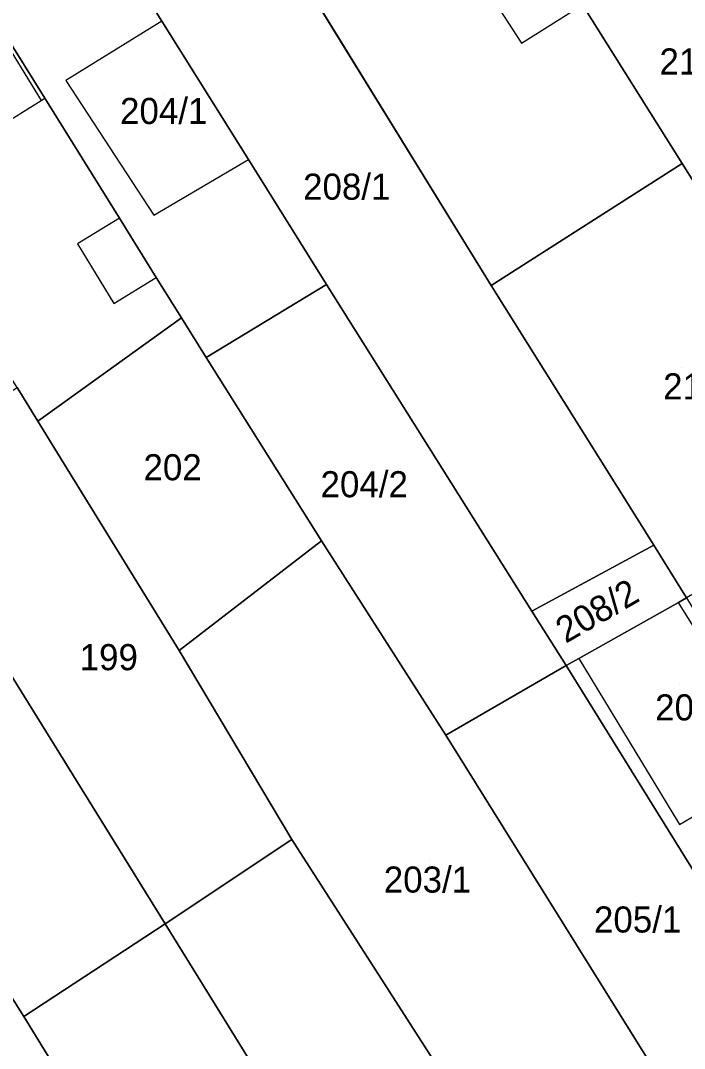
# Model space of a CAD drawing. Extents: x -263943 to -261149, y -1236934 to -1230686.
# Drawn here: x -262330.7 to -262279.9, y -1235708.9 to -1235630.2 of the extents above; entities that cross this region are included whole.
import ezdxf

# ---------------------------------------------------------------- set-up
doc = ezdxf.new("R2010")
doc.units = 0
for name, color, linetype in [('body_kn', 7, 'Continuous'), ('kladpar_druhypozemkov', 7, 'Continuous'), ('kladpar_hranice', 7, 'Continuous'), ('kladpar_parcelnecisla', 7, 'Continuous'), ('kladpar_plochy', 7, 'Continuous'), ('zappar_hrandruhpozemk', 7, 'Continuous')]:
    doc.layers.add(name, color=color, linetype=linetype)

msp = doc.modelspace()

# ---------------------------------------------------------------- linework, layer by layer
at = {"layer": 'body_kn'}
for p, q in [((-262319.91, -1235630.21), (-262319.91, -1235630.21)), ((-262319.91, -1235630.21), (-262319.91, -1235630.21)), ((-262292.36, -1235631.92), (-262292.36, -1235631.92)), ((-262327.26, -1235634.76), (-262327.26, -1235634.76)), ((-262327.26, -1235634.76), (-262327.26, -1235634.76)), ((-262329.16, -1235636.29), (-262329.16, -1235636.29)), ((-262329.16, -1235636.29), (-262329.16, -1235636.29)), ((-262328.88, -1235636.12), (-262328.88, -1235636.12)), ((-262313.29, -1235640.82), (-262313.29, -1235640.82)), ((-262280.06, -1235641.13), (-262280.06, -1235641.13)), ((-262280.06, -1235641.13), (-262280.06, -1235641.13)), ((-262323.16, -1235645.31), (-262323.16, -1235645.31)), ((-262323.16, -1235645.31), (-262323.16, -1235645.31)), ((-262320.54, -1235645.08), (-262320.54, -1235645.08)), ((-262326.38, -1235647.29), (-262326.38, -1235647.29)), ((-262320.34, -1235649.85), (-262320.34, -1235649.85)), ((-262307.31, -1235650.4), (-262307.31, -1235650.4)), ((-262307.31, -1235650.4), (-262307.31, -1235650.4)), ((-262294.69, -1235650.47), (-262294.69, -1235650.47)), ((-262323.58, -1235651.86), (-262323.58, -1235651.86)), ((-262318.41, -1235652.95), (-262318.41, -1235652.95)), ((-262318.41, -1235652.95), (-262318.41, -1235652.95)), ((-262316.53, -1235656), (-262316.53, -1235656)), ((-262329.41, -1235660.86), (-262329.41, -1235660.86)), ((-262328.1, -1235662.99), (-262328.1, -1235662.99)), ((-262307.69, -1235670.04), (-262307.69, -1235670.04)), ((-262307.69, -1235670.04), (-262307.69, -1235670.04)), ((-262282.25, -1235670.38), (-262282.25, -1235670.38)), ((-262280.36, -1235674.76), (-262280.36, -1235674.76)), ((-262291.57, -1235675.42), (-262291.57, -1235675.42)), ((-262318.6, -1235678.44), (-262318.6, -1235678.44)), ((-262318.6, -1235678.44), (-262318.6, -1235678.44)), ((-262287.99, -1235679.05), (-262287.99, -1235679.05)), ((-262287.99, -1235679.05), (-262287.99, -1235679.05)), ((-262288.95, -1235679.59), (-262288.95, -1235679.59)), ((-262298.17, -1235684.93), (-262298.17, -1235684.93)), ((-262298.17, -1235684.93), (-262298.17, -1235684.93)), ((-262280.28, -1235691.77), (-262280.28, -1235691.77)), ((-262309.95, -1235692.93), (-262309.95, -1235692.93)), ((-262309.95, -1235692.93), (-262309.95, -1235692.93)), ((-262319.66, -1235699.37), (-262319.66, -1235699.37)), ((-262330.48, -1235706.48), (-262330.48, -1235706.48)), ((-262330.48, -1235706.48), (-262330.48, -1235706.48))]:
    msp.add_line(p, q, dxfattribs=at)
at = {"layer": 'kladpar_druhypozemkov'}
for p, q in [((-262319.82, -1235635.85), (-262319.82, -1235635.85)), ((-262305.97, -1235641.7), (-262305.97, -1235641.7)), ((-262280.12, -1235656.75), (-262280.12, -1235656.75)), ((-262318.92, -1235663.3), (-262318.92, -1235663.3)), ((-262303.92, -1235664.3), (-262303.92, -1235664.3)), ((-262286.01, -1235674.27), (-262286.01, -1235674.27)), ((-262324.82, -1235678), (-262324.82, -1235678)), ((-262280.27, -1235680.95), (-262280.27, -1235680.95)), ((-262299.41, -1235694.45), (-262299.41, -1235694.45)), ((-262283.57, -1235697.7), (-262283.57, -1235697.7))]:
    msp.add_line(p, q, dxfattribs=at)
at = {"layer": 'kladpar_hranice'}
for points in [[(-262290.13, -1235625.13), (-262287.71, -1235628.98), (-262280.06, -1235641.13), (-262294.69, -1235650.47), (-262318.5, -1235611.81), (-262304.03, -1235603.06), (-262303.72, -1235603.55), (-262302.21, -1235605.94), (-262301.25, -1235607.46), (-262295.34, -1235616.87), (-262294.09, -1235618.85), (-262290.45, -1235624.62), (-262290.13, -1235625.13)], [(-262307.31, -1235650.4), (-262313.29, -1235640.82), (-262319.91, -1235630.21), (-262327.8, -1235617.58), (-262318.5, -1235611.81), (-262294.69, -1235650.47), (-262282.25, -1235670.38), (-262291.57, -1235675.42), (-262307.31, -1235650.4)], [(-262318.41, -1235652.95), (-262320.34, -1235649.85), (-262323.16, -1235645.31), (-262328.88, -1235636.12), (-262335.26, -1235625.87), (-262336.93, -1235623.19), (-262327.8, -1235617.58), (-262319.91, -1235630.21), (-262313.29, -1235640.82), (-262307.31, -1235650.4), (-262316.53, -1235656), (-262318.41, -1235652.95)], [(-262280.06, -1235641.13), (-262287.71, -1235628.98), (-262290.13, -1235625.13), (-262290.45, -1235624.62), (-262281.56, -1235618.72), (-262266.88, -1235641.83), (-262266.34, -1235642.68), (-262275.56, -1235648.31), (-262280.06, -1235641.13)], [(-262323.16, -1235645.31), (-262320.34, -1235649.85), (-262318.41, -1235652.95), (-262329.41, -1235660.86), (-262330.99, -1235658.3), (-262340.45, -1235643.42), (-262345.87, -1235634.63), (-262348.61, -1235630.18), (-262336.93, -1235623.19), (-262335.26, -1235625.87), (-262328.88, -1235636.12), (-262323.16, -1235645.31)], [(-262279.73, -1235674.41), (-262282.25, -1235670.38), (-262294.69, -1235650.47), (-262280.06, -1235641.13), (-262275.56, -1235648.31), (-262264.67, -1235665.67), (-262279.73, -1235674.41)], [(-262307.69, -1235670.04), (-262316.53, -1235656), (-262307.31, -1235650.4), (-262291.57, -1235675.42), (-262288.95, -1235679.59), (-262298.17, -1235684.93), (-262307.69, -1235670.04)], [(-262318.6, -1235678.44), (-262328.1, -1235662.99), (-262329.41, -1235660.86), (-262318.41, -1235652.95), (-262316.53, -1235656), (-262307.69, -1235670.04), (-262318.6, -1235678.44)], [(-262341.16, -1235664.74), (-262340.86, -1235664.55), (-262337.86, -1235662.65), (-262330.99, -1235658.3), (-262329.41, -1235660.86), (-262328.1, -1235662.99), (-262318.6, -1235678.44), (-262309.95, -1235692.93), (-262319.66, -1235699.37), (-262339.3, -1235667.72), (-262341.16, -1235664.74)], [(-262330.48, -1235706.48), (-262344.85, -1235683.73), (-262347.49, -1235679.41), (-262353.7, -1235669.41), (-262355.74, -1235666.13), (-262343.21, -1235661.46), (-262341.16, -1235664.74), (-262339.3, -1235667.72), (-262319.66, -1235699.37), (-262330.48, -1235706.48)], [(-262294.44, -1235717.17), (-262296.06, -1235714.61), (-262309.95, -1235692.93), (-262318.6, -1235678.44), (-262307.69, -1235670.04), (-262298.17, -1235684.93), (-262282.68, -1235709.8), (-262291.47, -1235715.31), (-262294.44, -1235717.17)], [(-262287.99, -1235679.05), (-262288.95, -1235679.59), (-262291.57, -1235675.42), (-262282.25, -1235670.38), (-262279.73, -1235674.41), (-262280.36, -1235674.76), (-262287.99, -1235679.05)], [(-262287.99, -1235679.05), (-262280.36, -1235674.76), (-262279.73, -1235674.41), (-262269.35, -1235691.58), (-262278.15, -1235697.01), (-262288.95, -1235679.59), (-262287.99, -1235679.05)], [(-262298.17, -1235684.93), (-262288.95, -1235679.59), (-262278.15, -1235697.01), (-262268.04, -1235713.09), (-262277.09, -1235718.77), (-262282.68, -1235709.8), (-262298.17, -1235684.93)], [(-262338.23, -1235728.59), (-262350.56, -1235709.05), (-262361.01, -1235692.39), (-262344.85, -1235683.73), (-262330.48, -1235706.48), (-262322.66, -1235719.26), (-262338.23, -1235728.59)], [(-262309.95, -1235692.93), (-262296.06, -1235714.61), (-262306.57, -1235720.55), (-262319.66, -1235699.37), (-262309.95, -1235692.93)], [(-262330.48, -1235706.48), (-262319.66, -1235699.37), (-262306.57, -1235720.55), (-262303.44, -1235725.52), (-262300.62, -1235730), (-262299.02, -1235732.55), (-262309.91, -1235739.73), (-262322.66, -1235719.26), (-262330.48, -1235706.48)]]:
    msp.add_lwpolyline(points, dxfattribs=at)
at = {"layer": 'kladpar_plochy'}
for p, q in [((-262318.5, -1235611.81), (-262294.69, -1235650.47)), ((-262319.91, -1235630.21), (-262327.8, -1235617.58)), ((-262313.29, -1235640.82), (-262319.91, -1235630.21)), ((-262307.31, -1235650.4), (-262313.29, -1235640.82)), ((-262291.57, -1235675.42), (-262307.31, -1235650.4)), ((-262294.69, -1235650.47), (-262282.25, -1235670.38)), ((-262282.25, -1235670.38), (-262291.57, -1235675.42))]:
    msp.add_line(p, q, dxfattribs=at)
for points in [[(-262290.13, -1235625.13), (-262287.71, -1235628.98), (-262280.06, -1235641.13), (-262294.69, -1235650.47), (-262318.5, -1235611.81), (-262304.03, -1235603.06), (-262303.72, -1235603.55), (-262302.21, -1235605.94), (-262301.25, -1235607.46), (-262295.34, -1235616.87), (-262294.09, -1235618.85), (-262290.45, -1235624.62)], [(-262318.41, -1235652.95), (-262320.34, -1235649.85), (-262323.16, -1235645.31), (-262328.88, -1235636.12), (-262335.26, -1235625.87), (-262336.93, -1235623.19), (-262327.8, -1235617.58), (-262319.91, -1235630.21), (-262313.29, -1235640.82), (-262307.31, -1235650.4), (-262316.53, -1235656)], [(-262280.06, -1235641.13), (-262287.71, -1235628.98), (-262290.13, -1235625.13), (-262290.45, -1235624.62), (-262281.56, -1235618.72), (-262266.88, -1235641.83), (-262266.34, -1235642.68), (-262275.56, -1235648.31)], [(-262323.16, -1235645.31), (-262320.34, -1235649.85), (-262318.41, -1235652.95), (-262329.41, -1235660.86), (-262330.99, -1235658.3), (-262340.45, -1235643.42), (-262345.87, -1235634.63), (-262348.61, -1235630.18), (-262336.93, -1235623.19), (-262335.26, -1235625.87), (-262328.88, -1235636.12)], [(-262279.73, -1235674.41), (-262282.25, -1235670.38), (-262294.69, -1235650.47), (-262280.06, -1235641.13), (-262275.56, -1235648.31), (-262264.67, -1235665.67)], [(-262307.69, -1235670.04), (-262316.53, -1235656), (-262307.31, -1235650.4), (-262291.57, -1235675.42), (-262288.95, -1235679.59), (-262298.17, -1235684.93)], [(-262318.6, -1235678.44), (-262328.1, -1235662.99), (-262329.41, -1235660.86), (-262318.41, -1235652.95), (-262316.53, -1235656), (-262307.69, -1235670.04)], [(-262341.16, -1235664.74), (-262340.86, -1235664.55), (-262337.86, -1235662.65), (-262330.99, -1235658.3), (-262329.41, -1235660.86), (-262328.1, -1235662.99), (-262318.6, -1235678.44), (-262309.95, -1235692.93), (-262319.66, -1235699.37), (-262339.3, -1235667.72)], [(-262330.48, -1235706.48), (-262344.85, -1235683.73), (-262347.49, -1235679.41), (-262353.7, -1235669.41), (-262355.74, -1235666.13), (-262343.21, -1235661.46), (-262341.16, -1235664.74), (-262339.3, -1235667.72), (-262319.66, -1235699.37)], [(-262294.44, -1235717.17), (-262296.06, -1235714.61), (-262309.95, -1235692.93), (-262318.6, -1235678.44), (-262307.69, -1235670.04), (-262298.17, -1235684.93), (-262282.68, -1235709.8), (-262291.47, -1235715.31)], [(-262287.99, -1235679.05), (-262288.95, -1235679.59), (-262291.57, -1235675.42), (-262282.25, -1235670.38), (-262279.73, -1235674.41), (-262280.36, -1235674.76)], [(-262287.99, -1235679.05), (-262280.36, -1235674.76), (-262279.73, -1235674.41), (-262269.35, -1235691.58), (-262278.15, -1235697.01), (-262288.95, -1235679.59)], [(-262298.17, -1235684.93), (-262288.95, -1235679.59), (-262278.15, -1235697.01), (-262268.04, -1235713.09), (-262277.09, -1235718.77), (-262282.68, -1235709.8)], [(-262338.23, -1235728.59), (-262350.56, -1235709.05), (-262361.01, -1235692.39), (-262344.85, -1235683.73), (-262330.48, -1235706.48), (-262322.66, -1235719.26)], [(-262309.95, -1235692.93), (-262296.06, -1235714.61), (-262306.57, -1235720.55), (-262319.66, -1235699.37)], [(-262330.48, -1235706.48), (-262319.66, -1235699.37), (-262306.57, -1235720.55), (-262303.44, -1235725.52), (-262300.62, -1235730), (-262299.02, -1235732.55), (-262309.91, -1235739.73), (-262322.66, -1235719.26)]]:
    msp.add_lwpolyline(points, close=True, dxfattribs=at)
at = {"layer": 'zappar_hrandruhpozemk'}
for p, q in [((-262335.48, -1235626.01), (-262329.16, -1235636.29)), ((-262319.91, -1235630.21), (-262327.26, -1235634.76)), ((-262336.9, -1235641.13), (-262329.16, -1235636.29)), ((-262329.16, -1235636.29), (-262328.88, -1235636.12)), ((-262323.16, -1235645.31), (-262326.38, -1235647.29)), ((-262326.38, -1235647.29), (-262323.58, -1235651.86)), ((-262323.58, -1235651.86), (-262320.34, -1235649.85)), ((-262272.58, -1235687.27), (-262280.36, -1235674.76)), ((-262287.99, -1235679.05), (-262280.28, -1235691.77)), ((-262280.28, -1235691.77), (-262272.58, -1235687.27))]:
    msp.add_line(p, q, dxfattribs=at)
for points in [[(-262294.81, -1235628.16), (-262292.36, -1235631.92), (-262287.71, -1235628.98)], [(-262327.26, -1235634.76), (-262320.54, -1235645.08), (-262313.29, -1235640.82)]]:
    msp.add_lwpolyline(points, dxfattribs=at)

# ---------------------------------------------------------------- texts
at = {"layer": 'kladpar_parcelnecisla'}
for s, p in [('212/3', (-262281.805, -1235634.31)), ('204/1', (-262323.118, -1235638.1)), ('208/1', (-262309.099, -1235643.9)), ('210', (-262281.528, -1235659.2)), ('202', (-262321.324, -1235665.4)), ('204/2', (-262307.764, -1235666.7)), ('199', (-262326.21, -1235679.95)), ('207', (-262282.14, -1235683.8)), ('203/1', (-262302.92, -1235696.99)), ('205/1', (-262286.823, -1235700.05))]:
    msp.add_text(s, height=2, dxfattribs=at).set_placement(p)
msp.add_text('208/2', height=2, rotation=30, dxfattribs=at).set_placement((-262288.992, -1235677.934))

doc.saveas('drawing.dxf')
